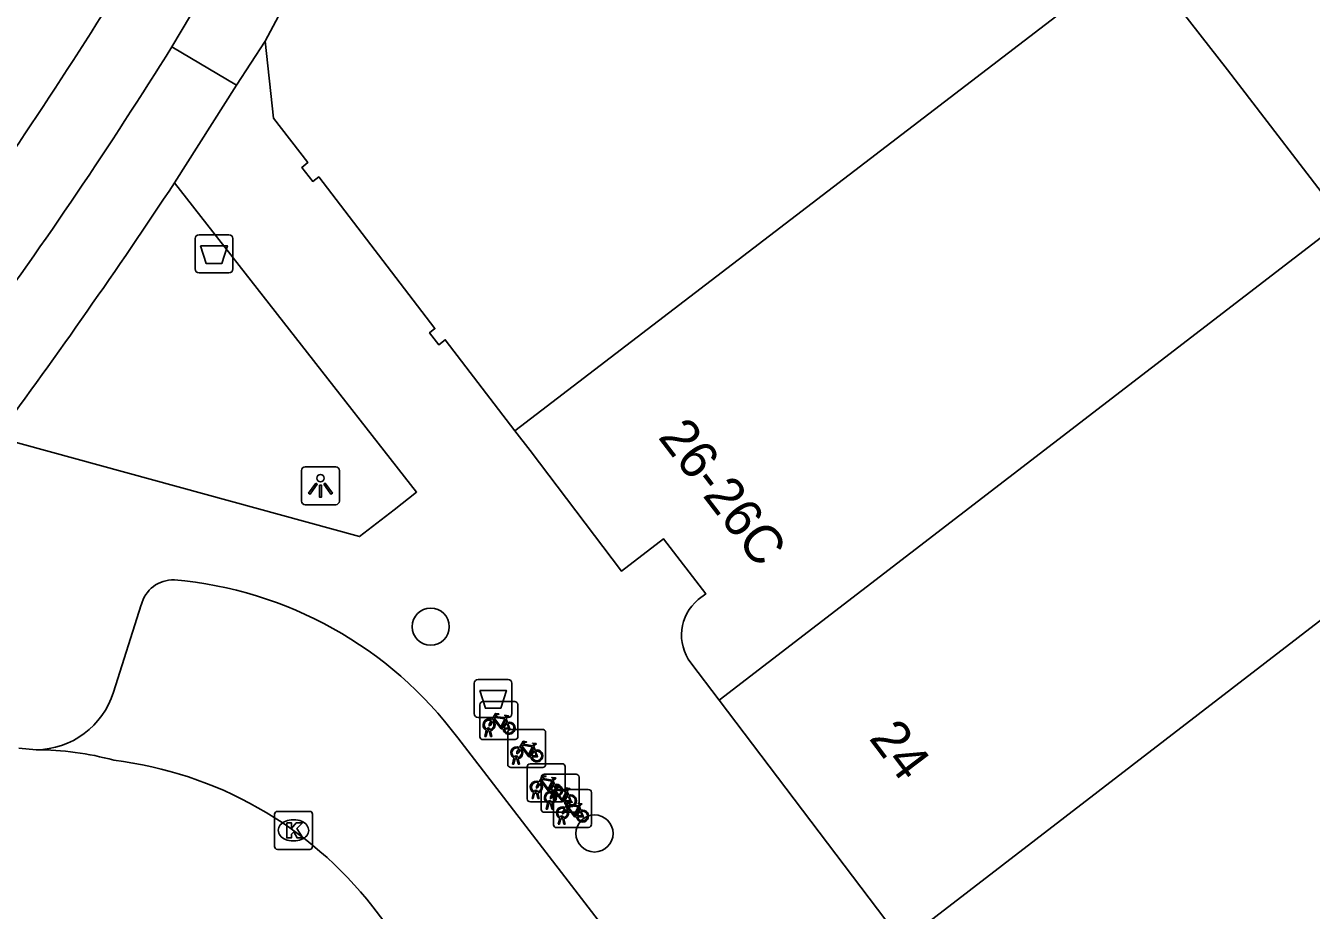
# Model space of a CAD drawing. Extents: x 160158 to 160921, y 381517 to 382041.
# Drawn here: x 160189.47 to 160223.34, y 381631.98 to 381655.28 of the extents above; entities that cross this region are included whole.
import ezdxf

# ---------------------------------------------------------------- set-up
doc = ezdxf.new("R2010")
doc.units = 0
for name, color, linetype in [('IMGEO_Afvalbak', 7, 'Continuous'), ('IMGEO_Boom', 7, 'Continuous'), ('IMGEO_Fietsenrek', 7, 'Continuous'), ('IMGEO_Kolk', 7, 'Continuous'), ('IMGEO_Lichtpunt', 7, 'Continuous'), ('IMGEO_Pand', 7, 'Continuous'), ('IMGEO_Pand_nummerreeks', 7, 'Continuous'), ('IMGEO_Rijbaan_lokaal_gesloten', 7, 'Continuous'), ('IMGEO_Rijbaan_lokaal_open', 7, 'Continuous'), ('IMGEO_Voetpad_open', 7, 'Continuous')]:
    doc.layers.add(name, color=color, linetype=linetype)

msp = doc.modelspace()

# ---------------------------------------------------------------- linework, layer by layer
at = {"layer": 'IMGEO_Afvalbak'}
for p, q in [((160193.937, 381648.875), (160193.937, 381649.675)), ((160193.937, 381649.675), (160193.937, 381648.875)), ((160194.037, 381649.775), (160194.827, 381649.775)), ((160194.827, 381649.775), (160194.037, 381649.775)), ((160194.927, 381649.675), (160194.927, 381648.875)), ((160194.927, 381648.875), (160194.927, 381649.675)), ((160194.827, 381648.775), (160194.037, 381648.775)), ((160194.037, 381648.775), (160194.827, 381648.775)), ((160201.388, 381638.063), (160202.178, 381638.063)), ((160202.178, 381638.063), (160201.388, 381638.063)), ((160201.288, 381637.163), (160201.288, 381637.963)), ((160201.288, 381637.963), (160201.288, 381637.163)), ((160202.278, 381637.963), (160202.278, 381637.163)), ((160202.278, 381637.163), (160202.278, 381637.963)), ((160202.178, 381637.063), (160201.388, 381637.063)), ((160201.388, 381637.063), (160202.178, 381637.063))]:
    msp.add_line(p, q, dxfattribs=at)
for points in [[(160194.08, 381649.489), (160194.784, 381649.489), (160194.635, 381649.019), (160194.229, 381649.019), (160194.08, 381649.489)], [(160201.431, 381637.777), (160202.135, 381637.777), (160201.986, 381637.307), (160201.58, 381637.307), (160201.431, 381637.777)]]:
    msp.add_lwpolyline(points, dxfattribs=at)
for centre, start, end in [((160194.037, 381649.675), 90, 180), ((160194.037, 381649.675), 90, 180), ((160194.827, 381649.675), 0, 90), ((160194.827, 381649.675), 360, 90), ((160194.037, 381648.875), 180, 270), ((160194.037, 381648.875), 180, 270), ((160194.827, 381648.875), 270, 0), ((160194.827, 381648.875), 270, 0), ((160201.388, 381637.963), 90, 180), ((160201.388, 381637.963), 90, 180), ((160202.178, 381637.963), 0, 90), ((160202.178, 381637.963), 360, 90), ((160201.388, 381637.163), 180, 270), ((160201.388, 381637.163), 180, 270), ((160202.178, 381637.163), 270, 0), ((160202.178, 381637.163), 270, 0)]:
    msp.add_arc(centre, 0.1, start, end, dxfattribs=at)
at = {"layer": 'IMGEO_Boom'}
for centre in [(160200.141, 381639.454), (160204.455, 381634.008)]:
    msp.add_circle(centre, 0.489, dxfattribs=at)
at = {"layer": 'IMGEO_Fietsenrek'}
for p, q in [((160201.438, 381636.555), (160201.438, 381637.396)), ((160201.438, 381637.396), (160201.438, 381636.555)), ((160201.513, 381637.48), (160202.354, 381637.48)), ((160202.354, 381637.48), (160201.513, 381637.48)), ((160202.438, 381637.405), (160202.438, 381636.564)), ((160202.438, 381636.564), (160202.438, 381637.405)), ((160202.125, 381637.029), (160202.161, 381636.934)), ((160201.565, 381636.564), (160201.604, 381636.724)), ((160201.634, 381636.712), (160201.599, 381636.564)), ((160201.676, 381636.736), (160201.675, 381636.74)), ((160201.717, 381636.564), (160201.683, 381636.706)), ((160201.707, 381636.747), (160201.708, 381636.74)), ((160201.715, 381636.71), (160201.75, 381636.564)), ((160202.243, 381636.748), (160203.084, 381636.748)), ((160203.084, 381636.748), (160202.243, 381636.748)), ((160202.363, 381636.48), (160201.522, 381636.48)), ((160201.522, 381636.48), (160202.363, 381636.48)), ((160201.599, 381636.564), (160201.565, 381636.564)), ((160201.75, 381636.564), (160201.717, 381636.564)), ((160202.168, 381635.823), (160202.168, 381636.664)), ((160202.168, 381636.664), (160202.168, 381635.823)), ((160203.168, 381636.673), (160203.168, 381635.832)), ((160203.168, 381635.832), (160203.168, 381636.673)), ((160202.406, 381636.004), (160202.405, 381636.008)), ((160202.437, 381636.015), (160202.438, 381636.008)), ((160202.855, 381636.297), (160202.891, 381636.202)), ((160203.093, 381635.748), (160202.252, 381635.748)), ((160202.252, 381635.748), (160203.093, 381635.748)), ((160202.295, 381635.832), (160202.334, 381635.992)), ((160202.329, 381635.832), (160202.295, 381635.832)), ((160202.364, 381635.98), (160202.329, 381635.832)), ((160202.447, 381635.832), (160202.413, 381635.974)), ((160202.445, 381635.978), (160202.48, 381635.832)), ((160202.48, 381635.832), (160202.447, 381635.832)), ((160202.682, 381634.917), (160202.682, 381635.758)), ((160202.682, 381635.758), (160202.682, 381634.917)), ((160202.757, 381635.842), (160203.598, 381635.842)), ((160203.598, 381635.842), (160202.757, 381635.842)), ((160203.682, 381635.767), (160203.682, 381634.926)), ((160203.682, 381634.926), (160203.682, 381635.767)), ((160203.052, 381634.641), (160203.052, 381635.482)), ((160203.052, 381635.482), (160203.052, 381634.641)), ((160203.127, 381635.566), (160203.968, 381635.566)), ((160203.968, 381635.566), (160203.127, 381635.566)), ((160203.369, 381635.391), (160203.405, 381635.296)), ((160204.052, 381635.491), (160204.052, 381634.65)), ((160204.052, 381634.65), (160204.052, 381635.491)), ((160202.809, 381634.926), (160202.848, 381635.086)), ((160202.878, 381635.074), (160202.843, 381634.926)), ((160202.92, 381635.098), (160202.919, 381635.102)), ((160202.961, 381634.926), (160202.927, 381635.068)), ((160202.951, 381635.109), (160202.952, 381635.102)), ((160202.959, 381635.072), (160202.994, 381634.926)), ((160203.372, 381634.239), (160203.372, 381635.08)), ((160203.372, 381635.08), (160203.372, 381634.239)), ((160203.447, 381635.164), (160204.288, 381635.164)), ((160204.288, 381635.164), (160203.447, 381635.164)), ((160203.739, 381635.115), (160203.775, 381635.02)), ((160204.372, 381635.089), (160204.372, 381634.248)), ((160204.372, 381634.248), (160204.372, 381635.089)), ((160203.607, 381634.842), (160202.766, 381634.842)), ((160202.766, 381634.842), (160203.607, 381634.842)), ((160202.843, 381634.926), (160202.809, 381634.926)), ((160202.994, 381634.926), (160202.961, 381634.926)), ((160203.179, 381634.65), (160203.218, 381634.81)), ((160203.213, 381634.65), (160203.179, 381634.65)), ((160203.248, 381634.798), (160203.213, 381634.65)), ((160203.29, 381634.822), (160203.289, 381634.826)), ((160203.331, 381634.65), (160203.297, 381634.792)), ((160203.321, 381634.833), (160203.322, 381634.826)), ((160203.329, 381634.796), (160203.364, 381634.65)), ((160203.364, 381634.65), (160203.331, 381634.65)), ((160204.059, 381634.713), (160204.095, 381634.618)), ((160203.977, 381634.566), (160203.136, 381634.566)), ((160203.136, 381634.566), (160203.977, 381634.566)), ((160203.499, 381634.248), (160203.538, 381634.408)), ((160203.568, 381634.396), (160203.533, 381634.248)), ((160203.61, 381634.42), (160203.609, 381634.424)), ((160203.651, 381634.248), (160203.617, 381634.39)), ((160203.641, 381634.431), (160203.642, 381634.424)), ((160203.649, 381634.394), (160203.684, 381634.248)), ((160204.297, 381634.164), (160203.456, 381634.164)), ((160203.456, 381634.164), (160204.297, 381634.164)), ((160203.533, 381634.248), (160203.499, 381634.248)), ((160203.684, 381634.248), (160203.651, 381634.248))]:
    msp.add_line(p, q, dxfattribs=at)
for points in [[(160201.751, 381637.006), (160201.846, 381637.17), (160201.932, 381637.156), (160201.934, 381637.147), (160201.878, 381637.136), (160201.851, 381637.091), (160202.107, 381637.05)], [(160202.094, 381637.025), (160201.837, 381637.066), (160201.82, 381637.037), (160201.987, 381636.817), (160202.094, 381637.025)], [(160202.107, 381637.05), (160202.132, 381637.099), (160202.126, 381637.103), (160202.103, 381637.107), (160202.091, 381637.114), (160202.09, 381637.117), (160202.092, 381637.122), (160202.187, 381637.107), (160202.189, 381637.097), (160202.179, 381637.084), (160202.167, 381637.078), (160202.153, 381637.084), (160202.125, 381637.029)], [(160201.772, 381636.954), (160201.72, 381636.864), (160201.68, 381636.839), (160201.681, 381636.886), (160201.736, 381636.98)], [(160202.047, 381636.762), (160201.997, 381636.762), (160201.806, 381637.013), (160201.787, 381636.981)], [(160202.142, 381636.927), (160202.112, 381637.004), (160202.003, 381636.786), (160202.046, 381636.786)], [(160202.076, 381636.786), (160202.196, 381636.785), (160202.152, 381636.899)], [(160202.172, 381636.906), (160202.227, 381636.761), (160202.077, 381636.761)], [(160202.481, 381636.274), (160202.576, 381636.438), (160202.662, 381636.424), (160202.664, 381636.415), (160202.608, 381636.404), (160202.581, 381636.359), (160202.837, 381636.318)], [(160202.837, 381636.318), (160202.862, 381636.367), (160202.856, 381636.371), (160202.833, 381636.375), (160202.821, 381636.382), (160202.82, 381636.385), (160202.822, 381636.39), (160202.917, 381636.375), (160202.919, 381636.365), (160202.909, 381636.352), (160202.897, 381636.346), (160202.883, 381636.352), (160202.855, 381636.297)], [(160202.502, 381636.222), (160202.45, 381636.132), (160202.41, 381636.107), (160202.411, 381636.154), (160202.466, 381636.248)], [(160202.777, 381636.03), (160202.727, 381636.03), (160202.536, 381636.281), (160202.517, 381636.249)], [(160202.824, 381636.293), (160202.567, 381636.334), (160202.55, 381636.305), (160202.717, 381636.085), (160202.824, 381636.293)], [(160202.872, 381636.195), (160202.842, 381636.272), (160202.733, 381636.054), (160202.776, 381636.054)], [(160202.806, 381636.054), (160202.926, 381636.053), (160202.882, 381636.167)], [(160202.902, 381636.174), (160202.957, 381636.029), (160202.807, 381636.029)], [(160203.016, 381635.316), (160202.964, 381635.226), (160202.924, 381635.201), (160202.925, 381635.248), (160202.98, 381635.342)], [(160202.995, 381635.368), (160203.09, 381635.532), (160203.176, 381635.518), (160203.178, 381635.509), (160203.122, 381635.498), (160203.095, 381635.453), (160203.351, 381635.412)], [(160203.291, 381635.124), (160203.241, 381635.124), (160203.05, 381635.375), (160203.031, 381635.343)], [(160203.338, 381635.387), (160203.081, 381635.428), (160203.064, 381635.399), (160203.231, 381635.179), (160203.338, 381635.387)], [(160203.386, 381635.289), (160203.356, 381635.366), (160203.247, 381635.148), (160203.29, 381635.148)], [(160203.351, 381635.412), (160203.376, 381635.461), (160203.37, 381635.465), (160203.347, 381635.469), (160203.335, 381635.476), (160203.334, 381635.479), (160203.336, 381635.484), (160203.431, 381635.469), (160203.433, 381635.459), (160203.423, 381635.446), (160203.411, 381635.44), (160203.397, 381635.446), (160203.369, 381635.391)], [(160203.386, 381635.04), (160203.334, 381634.95), (160203.294, 381634.925), (160203.295, 381634.972), (160203.35, 381635.066)], [(160203.32, 381635.148), (160203.44, 381635.147), (160203.396, 381635.261)], [(160203.416, 381635.268), (160203.471, 381635.123), (160203.321, 381635.123)], [(160203.365, 381635.092), (160203.46, 381635.256), (160203.546, 381635.242), (160203.548, 381635.233), (160203.492, 381635.222), (160203.465, 381635.177), (160203.721, 381635.136)], [(160203.661, 381634.848), (160203.611, 381634.848), (160203.42, 381635.099), (160203.401, 381635.067)], [(160203.708, 381635.111), (160203.451, 381635.152), (160203.434, 381635.123), (160203.601, 381634.903), (160203.708, 381635.111)], [(160203.756, 381635.013), (160203.726, 381635.09), (160203.617, 381634.872), (160203.66, 381634.872)], [(160203.786, 381634.992), (160203.841, 381634.847), (160203.691, 381634.847)], [(160203.721, 381635.136), (160203.746, 381635.185), (160203.74, 381635.189), (160203.717, 381635.193), (160203.705, 381635.2), (160203.704, 381635.203), (160203.706, 381635.208), (160203.801, 381635.193), (160203.803, 381635.183), (160203.793, 381635.17), (160203.781, 381635.164), (160203.767, 381635.17), (160203.739, 381635.115)], [(160203.706, 381634.638), (160203.654, 381634.548), (160203.614, 381634.523), (160203.615, 381634.57), (160203.67, 381634.664)], [(160203.685, 381634.69), (160203.78, 381634.854), (160203.866, 381634.84), (160203.868, 381634.831), (160203.812, 381634.82), (160203.785, 381634.775), (160204.041, 381634.734)], [(160203.69, 381634.872), (160203.81, 381634.871), (160203.766, 381634.985)], [(160203.981, 381634.446), (160203.931, 381634.446), (160203.74, 381634.697), (160203.721, 381634.665)], [(160204.028, 381634.709), (160203.771, 381634.75), (160203.754, 381634.721), (160203.921, 381634.501), (160204.028, 381634.709)], [(160204.076, 381634.611), (160204.046, 381634.688), (160203.937, 381634.47), (160203.98, 381634.47)], [(160204.041, 381634.734), (160204.066, 381634.783), (160204.06, 381634.787), (160204.037, 381634.791), (160204.025, 381634.798), (160204.024, 381634.801), (160204.026, 381634.806), (160204.121, 381634.791), (160204.123, 381634.781), (160204.113, 381634.768), (160204.101, 381634.762), (160204.087, 381634.768), (160204.059, 381634.713)], [(160204.01, 381634.47), (160204.13, 381634.469), (160204.086, 381634.583)], [(160204.106, 381634.59), (160204.161, 381634.445), (160204.011, 381634.445)]]:
    msp.add_lwpolyline(points, dxfattribs=at)
for centre, radius, start, end in [((160201.516, 381637.402), 0.0779, 92.4484, 184.2845), ((160201.516, 381637.402), 0.0779, 92.4484, 184.2845), ((160202.36, 381637.402), 0.0779, 2.4484, 94.2845), ((160202.36, 381637.402), 0.0779, 2.4484, 94.2845), ((160201.678, 381636.865), 0.159, 62.6766, 242.1369), ((160201.678, 381636.865), 0.129, 63.3192, 238.903), ((160201.658, 381636.736), 0.0499, 12.8025, 158.6934), ((160201.678, 381636.865), 0.159, 253.9967, 271.7867), ((160201.658, 381636.736), 0.0174, 12.8025, 163.4502), ((160201.678, 381636.865), 0.129, 253.415, 269.0204), ((160201.678, 381636.865), 0.129, 283.6043, 43.4302), ((160201.678, 381636.865), 0.159, 283.5766, 46.6042), ((160202.205, 381636.781), 0.159, 113.3408, 178.3217), ((160202.205, 381636.781), 0.159, 187.0065, 105.7708), ((160202.205, 381636.781), 0.129, 113.923, 177.9556), ((160202.205, 381636.781), 0.129, 188.6715, 104.5883), ((160202.246, 381636.67), 0.0779, 92.4484, 184.2845), ((160202.246, 381636.67), 0.0779, 92.4484, 184.2845), ((160203.09, 381636.67), 0.0779, 2.4484, 94.2845), ((160203.09, 381636.67), 0.0779, 2.4484, 94.2845), ((160201.516, 381636.558), 0.0779, 182.4484, 274.2845), ((160201.516, 381636.558), 0.0779, 182.4484, 274.2845), ((160202.36, 381636.558), 0.0779, 272.4484, 4.2845), ((160202.36, 381636.558), 0.0779, 272.4484, 4.2845), ((160202.408, 381636.133), 0.159, 62.6766, 242.1369), ((160202.408, 381636.133), 0.129, 63.3192, 238.903), ((160202.388, 381636.004), 0.0499, 12.8025, 158.6934), ((160202.388, 381636.004), 0.0174, 12.8025, 163.4502), ((160202.408, 381636.133), 0.129, 253.415, 269.0204), ((160202.408, 381636.133), 0.129, 283.6043, 43.4302), ((160202.408, 381636.133), 0.159, 283.5766, 46.6042), ((160202.935, 381636.049), 0.159, 113.3408, 178.3217), ((160202.935, 381636.049), 0.159, 187.0065, 105.7708), ((160202.935, 381636.049), 0.129, 113.923, 177.9556), ((160202.935, 381636.049), 0.129, 188.6715, 104.5883), ((160202.246, 381635.826), 0.0779, 182.4484, 274.2845), ((160202.246, 381635.826), 0.0779, 182.4484, 274.2845), ((160202.408, 381636.133), 0.159, 253.9967, 271.7867), ((160202.76, 381635.764), 0.0779, 92.4484, 184.2845), ((160202.76, 381635.764), 0.0779, 92.4484, 184.2845), ((160203.09, 381635.826), 0.0779, 272.4484, 4.2845), ((160203.09, 381635.826), 0.0779, 272.4484, 4.2845), ((160203.604, 381635.764), 0.0779, 2.4484, 94.2845), ((160203.604, 381635.764), 0.0779, 2.4484, 94.2845), ((160202.922, 381635.227), 0.159, 62.6766, 242.1369), ((160202.922, 381635.227), 0.129, 63.3192, 238.903), ((160202.922, 381635.227), 0.159, 283.5766, 46.6042), ((160203.13, 381635.488), 0.0779, 92.4484, 184.2845), ((160203.13, 381635.488), 0.0779, 92.4484, 184.2845), ((160203.974, 381635.488), 0.0779, 2.4484, 94.2845), ((160203.974, 381635.488), 0.0779, 2.4484, 94.2845), ((160202.902, 381635.098), 0.0499, 12.8025, 158.6934), ((160202.922, 381635.227), 0.159, 253.9967, 271.7867), ((160202.902, 381635.098), 0.0174, 12.8025, 163.4502), ((160202.922, 381635.227), 0.129, 253.415, 269.0204), ((160202.922, 381635.227), 0.129, 283.6043, 43.4302), ((160203.292, 381634.951), 0.159, 62.6766, 242.1369), ((160203.292, 381634.951), 0.129, 63.3192, 238.903), ((160203.449, 381635.143), 0.159, 113.3408, 178.3217), ((160203.449, 381635.143), 0.159, 187.0065, 105.7708), ((160203.449, 381635.143), 0.129, 113.923, 177.9556), ((160203.449, 381635.143), 0.129, 188.6715, 104.5883), ((160203.292, 381634.951), 0.129, 283.6043, 43.4302), ((160203.292, 381634.951), 0.159, 283.5766, 46.6042), ((160203.45, 381635.086), 0.0779, 92.4484, 184.2845), ((160203.45, 381635.086), 0.0779, 92.4484, 184.2845), ((160203.819, 381634.867), 0.159, 113.3408, 178.3217), ((160203.819, 381634.867), 0.159, 187.0065, 105.7708), ((160203.819, 381634.867), 0.129, 188.6715, 104.5883), ((160204.294, 381635.086), 0.0779, 2.4484, 94.2845), ((160204.294, 381635.086), 0.0779, 2.4484, 94.2845), ((160202.76, 381634.92), 0.0779, 182.4484, 274.2845), ((160202.76, 381634.92), 0.0779, 182.4484, 274.2845), ((160203.272, 381634.822), 0.0499, 12.8025, 158.6934), ((160203.292, 381634.951), 0.159, 253.9967, 271.7867), ((160203.272, 381634.822), 0.0174, 12.8025, 163.4502), ((160203.292, 381634.951), 0.129, 253.415, 269.0204), ((160203.612, 381634.549), 0.159, 62.6766, 242.1369), ((160203.612, 381634.549), 0.129, 63.3192, 238.903), ((160203.604, 381634.92), 0.0779, 272.4484, 4.2845), ((160203.604, 381634.92), 0.0779, 272.4484, 4.2845), ((160203.612, 381634.549), 0.159, 283.5766, 46.6042), ((160203.819, 381634.867), 0.129, 113.923, 177.9556), ((160203.974, 381634.644), 0.0779, 272.4484, 4.2845), ((160203.974, 381634.644), 0.0779, 272.4484, 4.2845), ((160203.13, 381634.644), 0.0779, 182.4484, 274.2845), ((160203.13, 381634.644), 0.0779, 182.4484, 274.2845), ((160203.592, 381634.42), 0.0499, 12.8025, 158.6934), ((160203.612, 381634.549), 0.159, 253.9967, 271.7867), ((160203.592, 381634.42), 0.0174, 12.8025, 163.4502), ((160203.612, 381634.549), 0.129, 253.415, 269.0204), ((160203.612, 381634.549), 0.129, 283.6043, 43.4302), ((160204.139, 381634.465), 0.159, 113.3408, 178.3217), ((160204.139, 381634.465), 0.159, 187.0065, 105.7708), ((160204.139, 381634.465), 0.129, 113.923, 177.9556), ((160204.139, 381634.465), 0.129, 188.6715, 104.5883), ((160203.45, 381634.242), 0.0779, 182.4484, 274.2845), ((160203.45, 381634.242), 0.0779, 182.4484, 274.2845), ((160204.294, 381634.242), 0.0779, 272.4484, 4.2845), ((160204.294, 381634.242), 0.0779, 272.4484, 4.2845)]:
    msp.add_arc(centre, radius, start, end, dxfattribs=at)
at = {"layer": 'IMGEO_Kolk'}
for p, q in [((160196.026, 381633.663), (160196.026, 381634.515)), ((160196.101, 381634.589), (160196.953, 381634.589)), ((160196.514, 381634.369), (160196.539, 381634.369)), ((160197.027, 381634.515), (160197.027, 381633.663)), ((160196.537, 381633.809), (160196.512, 381633.809)), ((160196.953, 381633.589), (160196.101, 381633.589))]:
    msp.add_line(p, q, dxfattribs=at)
for points in [[(160196.026, 381633.663), (160196.026, 381634.515)], [(160196.101, 381634.589), (160196.953, 381634.589)], [(160197.027, 381634.515), (160197.027, 381633.663)], [(160196.347, 381634.289), (160196.47, 381634.289), (160196.47, 381634.138), (160196.6, 381634.289), (160196.764, 381634.289), (160196.618, 381634.138), (160196.771, 381633.889), (160196.619, 381633.889), (160196.534, 381634.053), (160196.47, 381633.986), (160196.47, 381633.889), (160196.347, 381633.889), (160196.347, 381634.289)], [(160196.953, 381633.589), (160196.101, 381633.589)]]:
    msp.add_lwpolyline(points, dxfattribs=at)
for centre, start, end in [((160196.103, 381634.513), 91.552, 178.448), ((160196.103, 381634.513), 91.552, 178.448), ((160196.951, 381634.513), 1.552, 88.448), ((160196.951, 381634.513), 1.552, 88.448), ((160196.103, 381633.665), 181.552, 268.448), ((160196.103, 381633.665), 181.552, 268.448), ((160196.951, 381633.665), 271.552, 358.448), ((160196.951, 381633.665), 271.552, 358.448)]:
    msp.add_arc(centre, 0.0765, start, end, dxfattribs=at)
for centre, major_axis, ratio, start_param, end_param in [((160196.513, 381634.089), (-0.387, 0.002), 0.722429, 4.712389, 7.853982), ((160196.538, 381634.089), (-0.39, 0.002), 0.717154, 1.570796, 4.712389)]:
    msp.add_ellipse(centre, major_axis=major_axis, ratio=ratio, start_param=start_param, end_param=end_param, dxfattribs=at)
at = {"layer": 'IMGEO_Lichtpunt'}
for p, q in [((160196.738, 381643.568), (160196.738, 381642.761)), ((160196.738, 381643.568), (160196.738, 381642.761)), ((160197.64, 381643.663), (160196.832, 381643.663)), ((160197.64, 381643.663), (160196.832, 381643.663)), ((160197.734, 381642.761), (160197.734, 381643.568)), ((160197.734, 381642.761), (160197.734, 381643.568)), ((160196.832, 381642.667), (160197.64, 381642.667)), ((160196.832, 381642.667), (160197.64, 381642.667))]:
    msp.add_line(p, q, dxfattribs=at)
for points in [[(160197.112, 381643.232), (160197.151, 381643.204), (160196.963, 381642.942), (160196.925, 381642.969), (160197.112, 381643.232)], [(160197.214, 381643.184), (160197.261, 381643.184), (160197.261, 381642.862), (160197.214, 381642.862), (160197.214, 381643.184)], [(160197.324, 381643.204), (160197.362, 381643.231), (160197.549, 381642.969), (160197.51, 381642.941), (160197.324, 381643.204)]]:
    msp.add_lwpolyline(points, dxfattribs=at)
msp.add_circle((160197.237, 381643.366), 0.0994, dxfattribs=at)
for centre, start, end in [((160196.832, 381643.568), 90, 180), ((160196.832, 381643.568), 90, 180), ((160197.64, 381643.568), 0, 90), ((160197.64, 381643.568), 0, 90), ((160196.832, 381642.761), 180, 270), ((160196.832, 381642.761), 180, 270), ((160197.64, 381642.761), 270, 0), ((160197.64, 381642.761), 270, 360)]:
    msp.add_arc(centre, 0.0946, start, end, dxfattribs=at)
at = {"layer": 'IMGEO_Pand'}
for points in [[(160201.164, 381665.334), (160196.27, 381656.144), (160196.413, 381656.068), (160195.783, 381654.876)], [(160217.867, 381656.496), (160218.753, 381657.175), (160221.132, 381654.122), (160224.171, 381650.152)], [(160202.359, 381644.613), (160217.867, 381656.496)], [(160195.783, 381654.876), (160195.998, 381652.849), (160196.903, 381651.679), (160196.747, 381651.552), (160197.031, 381651.181), (160197.19, 381651.302), (160200.253, 381647.307), (160200.11, 381647.197), (160200.354, 381646.879), (160200.523, 381647.009), (160202.359, 381644.613)], [(160224.171, 381650.152), (160207.737, 381637.521)], [(160202.359, 381644.613), (160202.756, 381644.095), (160205.162, 381640.92), (160206.27, 381641.769), (160207.383, 381640.317), (160207.187, 381640.166)], [(160212.568, 381631.144), (160229.025, 381643.813)], [(160206.994, 381638.502), (160207.737, 381637.521)], [(160207.737, 381637.521), (160212.568, 381631.144)]]:
    msp.add_lwpolyline(points, dxfattribs=at)
msp.add_arc((160207.952, 381639.234), 1.206, 129.3847, 217.3835, dxfattribs=at)
at = {"layer": 'IMGEO_Rijbaan_lokaal_gesloten'}
msp.add_arc((160071.591, 381731.31), 141.817, 323.27741, 330.77664, dxfattribs=at)
at = {"layer": 'IMGEO_Rijbaan_lokaal_open'}
for points in [[(160189.745, 381636.212), (160189.291, 381636.255)], [(160198.612, 381632.076), (160205.152, 381623.558), (160213.703, 381612.526), (160222.274, 381601.404), (160224.654, 381598.332)]]:
    msp.add_lwpolyline(points, dxfattribs=at)
for centre, radius, start, end in [((160189.75, 381628.506), 7.706, 74.6193, 90.0376), ((160190.558, 381625.801), 10.21, 37.9218, 83.0456)]:
    msp.add_arc(centre, radius, start, end, dxfattribs=at)
at = {"layer": 'IMGEO_Voetpad_open'}
for points in [[(160197.756, 381662.253), (160196.245, 381659.639), (160193.32, 381654.723)], [(160195.029, 381653.713), (160193.32, 381654.723)], [(160195.029, 381653.713), (160195.783, 381654.876)], [(160193.389, 381651.141), (160195.029, 381653.713)], [(160188.705, 381644.442), (160198.267, 381641.825), (160199.175, 381642.535), (160199.769, 381643), (160193.389, 381651.141)], [(160192.514, 381640.025), (160191.784, 381637.727)], [(160228.264, 381600.92), (160200.851, 381636.528)]]:
    msp.add_lwpolyline(points, dxfattribs=at)
for centre, radius, start, end in [((160082.645, 381723.888), 130.51, 319.93904, 327.99702), ((160057.705, 381741.025), 162.755, 323.59946, 326.47736), ((160193.362, 381639.815), 0.873, 88.264, 166.1025), ((160192.478, 381630.281), 10.447, 36.7256, 85.0023), ((160189.723, 381638.371), 2.159, 270.5786, 342.6469)]:
    msp.add_arc(centre, radius, start, end, dxfattribs=at)

# ---------------------------------------------------------------- texts
at = {"layer": 'IMGEO_Pand_nummerreeks'}
for s, rotation, p in [('26-26C', 307.4712, (160206.108, 381644.444)), ('24', 307.1496, (160211.664, 381636.511))]:
    msp.add_text(s, height=1, rotation=rotation, dxfattribs=at).set_placement(p)

doc.saveas('drawing.dxf')
